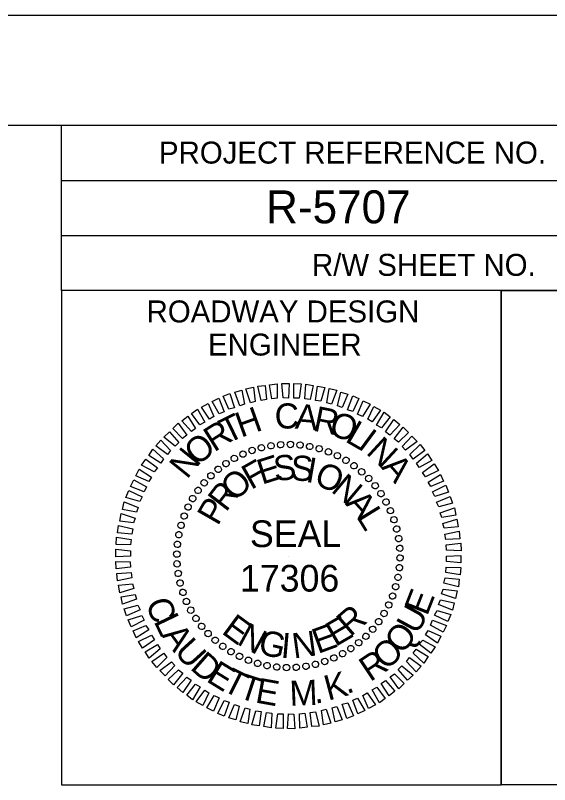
# Model space of a CAD drawing. Extents: x 573078 to 573117.1, y -55221.3 to -55199.3.
# Drawn here: x 573107.304 to 573109.734, y -55202.8 to -55199.298 of the extents above; entities that cross this region are included whole.
import ezdxf

# ---------------------------------------------------------------- set-up
doc = ezdxf.new("R2010")
doc.units = 0
for name, color, linetype in [('Prop Dimension', 7, 'Continuous'), ('Scratch_Level_1', 7, 'Continuous'), ('Sheet Data Field CELL', 7, 'Continuous'), ('Sheet Plan CELL', 7, 'Continuous'), ('Sheet Plot Border Inside CELL', 7, 'Continuous')]:
    doc.layers.add(name, color=color, linetype=linetype)

msp = doc.modelspace()

# ---------------------------------------------------------------- linework, layer by layer
at = {"layer": 'Prop Dimension'}
for p, q in [((573108.5105, -55201.2518), (573108.5105, -55201.2518)), ((573108.555, -55201.2509), (573108.555, -55201.2509)), ((573108.5996, -55201.2539), (573108.5996, -55201.2539)), ((573108.38, -55201.2782), (573108.38, -55201.2782)), ((573108.4225, -55201.266), (573108.4225, -55201.266)), ((573108.467, -55201.2579), (573108.467, -55201.2579)), ((573108.6432, -55201.2611), (573108.6432, -55201.2611)), ((573108.6857, -55201.2701), (573108.6857, -55201.2701)), ((573108.7283, -55201.2842), (573108.7283, -55201.2842)), ((573108.2999, -55201.3146), (573108.2999, -55201.3146)), ((573108.3395, -55201.2944), (573108.3395, -55201.2944)), ((573108.7688, -55201.3025), (573108.7688, -55201.3025)), ((573108.8081, -55201.3227), (573108.8081, -55201.3227)), ((573108.2614, -55201.338), (573108.2614, -55201.338)), ((573108.8446, -55201.3481), (573108.8446, -55201.3481)), ((573108.1925, -55201.3936), (573108.1925, -55201.3936)), ((573108.2261, -55201.3632), (573108.2261, -55201.3632)), ((573108.8801, -55201.3754), (573108.8801, -55201.3754)), ((573108.1622, -55201.4251), (573108.1622, -55201.4251)), ((573108.9114, -55201.4057), (573108.9114, -55201.4057)), ((573108.1349, -55201.4604), (573108.1349, -55201.4604)), ((573108.9418, -55201.4393), (573108.9418, -55201.4393)), ((573108.1095, -55201.4969), (573108.1095, -55201.4969)), ((573108.9672, -55201.4746), (573108.9672, -55201.4746)), ((573108.0893, -55201.5365), (573108.0893, -55201.5365)), ((573108.9904, -55201.5131), (573108.9904, -55201.5131)), ((573109.0106, -55201.5527), (573109.0106, -55201.5527)), ((573108.071, -55201.577), (573108.071, -55201.577)), ((573109.0268, -55201.5932), (573109.0268, -55201.5932)), ((573108.0569, -55201.6195), (573108.0569, -55201.6195)), ((573109.039, -55201.6357), (573109.039, -55201.6357)), ((573108.0479, -55201.662), (573108.0479, -55201.662)), ((573108.0407, -55201.7054), (573108.0407, -55201.7054)), ((573109.0471, -55201.6802), (573109.0471, -55201.6802)), ((573109.0532, -55201.7237), (573109.0532, -55201.7237)), ((573108.0377, -55201.75), (573108.0377, -55201.75)), ((573108.546, -55201.7592), (573108.546, -55201.7592)), ((573109.0543, -55201.7682), (573109.0543, -55201.7682)), ((573108.0386, -55201.7945), (573108.0386, -55201.7945)), ((573109.0511, -55201.8128), (573109.0511, -55201.8128)), ((573108.0447, -55201.8382), (573108.0447, -55201.8382)), ((573108.0528, -55201.8827), (573108.0528, -55201.8827)), ((573109.0442, -55201.8564), (573109.0442, -55201.8564)), ((573109.0349, -55201.8989), (573109.0349, -55201.8989)), ((573108.065, -55201.9253), (573108.065, -55201.9253)), ((573109.0208, -55201.9415), (573109.0208, -55201.9415)), ((573108.0812, -55201.9658), (573108.0812, -55201.9658)), ((573109.0025, -55201.982), (573109.0025, -55201.982)), ((573108.1014, -55202.0051), (573108.1014, -55202.0051)), ((573108.9823, -55202.0213), (573108.9823, -55202.0213)), ((573108.1248, -55202.0436), (573108.1248, -55202.0436)), ((573108.9571, -55202.0578), (573108.9571, -55202.0578)), ((573108.15, -55202.0792), (573108.15, -55202.0792)), ((573108.9296, -55202.0933), (573108.9296, -55202.0933)), ((573108.1804, -55202.1125), (573108.1804, -55202.1125)), ((573108.8993, -55202.1246), (573108.8993, -55202.1246)), ((573108.2119, -55202.1428), (573108.2119, -55202.1428)), ((573108.866, -55202.155), (573108.866, -55202.155)), ((573108.2472, -55202.1703), (573108.2472, -55202.1703)), ((573108.2837, -55202.1955), (573108.2837, -55202.1955)), ((573108.8304, -55202.1804), (573108.8304, -55202.1804)), ((573108.3233, -55202.2157), (573108.3233, -55202.2157)), ((573108.3638, -55202.234), (573108.3638, -55202.234)), ((573108.7526, -55202.2238), (573108.7526, -55202.2238)), ((573108.7919, -55202.2036), (573108.7919, -55202.2036)), ((573108.4063, -55202.2481), (573108.4063, -55202.2481)), ((573108.4488, -55202.2574), (573108.4488, -55202.2574)), ((573108.4922, -55202.2643), (573108.4922, -55202.2643)), ((573108.5368, -55202.2675), (573108.5368, -55202.2675)), ((573108.5813, -55202.2664), (573108.5813, -55202.2664)), ((573108.625, -55202.2603), (573108.625, -55202.2603)), ((573108.6695, -55202.2522), (573108.6695, -55202.2522)), ((573108.7121, -55202.24), (573108.7121, -55202.24))]:
    msp.add_line(p, q, dxfattribs=at)
for points in [[(573108.4711, -55201.0444), (573108.4598, -55200.9796), (573108.4943, -55200.9755), (573108.4954, -55201.0412)], [(573108.5217, -55201.0392), (573108.5165, -55200.9735), (573108.5501, -55200.9744), (573108.546, -55201.0403)], [(573108.5703, -55201.0403), (573108.5703, -55200.9744), (573108.6036, -55200.9755), (573108.5946, -55201.0412)], [(573108.3253, -55201.0748), (573108.3019, -55201.014), (573108.3334, -55201.0048), (573108.3464, -55201.0676)], [(573108.3739, -55201.0615), (573108.3525, -55200.9978), (573108.3869, -55200.9906), (573108.395, -55201.0565)], [(573108.4225, -55201.0505), (573108.4063, -55200.9857), (573108.4396, -55200.9825), (573108.4468, -55201.0473)], [(573108.6209, -55201.0433), (573108.625, -55200.9776), (573108.6583, -55200.9836), (573108.6452, -55201.0473)], [(573108.6695, -55201.0514), (573108.6785, -55200.9866), (573108.7121, -55200.9917), (573108.6938, -55201.0545)], [(573108.7211, -55201.0626), (573108.7312, -55200.9967), (573108.7656, -55201.0048), (573108.7424, -55201.0676)], [(573108.231, -55201.1121), (573108.1986, -55201.0554), (573108.2301, -55201.0412), (573108.2533, -55201.1031)], [(573108.2756, -55201.091), (573108.2492, -55201.0322), (573108.2796, -55201.0201), (573108.301, -55201.0849)], [(573108.7697, -55201.0757), (573108.785, -55201.0129), (573108.8162, -55201.023), (573108.791, -55201.0829)], [(573108.8153, -55201.0939), (573108.8385, -55201.0302), (573108.8669, -55201.0424), (573108.8385, -55201.1011)], [(573108.1876, -55201.1364), (573108.15, -55201.0817), (573108.1815, -55201.0655), (573108.2067, -55201.1243)], [(573108.8608, -55201.1132), (573108.8862, -55201.0534), (573108.9175, -55201.0676), (573108.8831, -55201.1243)], [(573108.9074, -55201.1364), (573108.9348, -55201.0788), (573108.9652, -55201.0959), (573108.9267, -55201.1486)], [(573108.143, -55201.1618), (573108.1055, -55201.1101), (573108.1318, -55201.091), (573108.1653, -55201.1497)], [(573108.947, -55201.1639), (573108.9823, -55201.1051), (573109.0086, -55201.1263), (573108.9692, -55201.176)], [(573108.1046, -55201.1922), (573108.0609, -55201.1436), (573108.0884, -55201.1222), (573108.1237, -55201.1789)], [(573108.9884, -55201.1942), (573109.0259, -55201.1384), (573109.0523, -55201.1607), (573109.0077, -55201.2084)], [(573108.0641, -55201.2235), (573108.0195, -55201.1789), (573108.0438, -55201.1546), (573108.0832, -55201.2093)], [(573109.0268, -55201.2255), (573109.0685, -55201.1729), (573109.0928, -55201.1972), (573109.0462, -55201.2408)], [(573108.0305, -55201.259), (573107.979, -55201.2174), (573108.0042, -55201.1942), (573108.0467, -55201.2428)], [(573109.0633, -55201.2611), (573109.1069, -55201.2134), (573109.1312, -55201.2377), (573109.0786, -55201.2773)], [(573107.9952, -55201.2975), (573107.9426, -55201.2579), (573107.9648, -55201.2316), (573108.0094, -55201.2793)], [(573109.0988, -55201.2975), (573109.1454, -55201.2518), (573109.1666, -55201.2793), (573109.113, -55201.3178)], [(573107.9648, -55201.336), (573107.9102, -55201.3016), (573107.9293, -55201.2721), (573107.9779, -55201.3166)], [(573107.9345, -55201.3765), (573107.8778, -55201.3461), (573107.898, -55201.3178), (573107.9507, -55201.3583)], [(573109.1292, -55201.3369), (573109.1787, -55201.2944), (573109.1981, -55201.3238), (573109.1414, -55201.3562)], [(573109.1555, -55201.3785), (573109.2091, -55201.34), (573109.2284, -55201.3704), (573109.1697, -55201.3988)], [(573107.9102, -55201.4199), (573107.8523, -55201.3947), (573107.8676, -55201.3632), (573107.9223, -55201.4008)], [(573109.1819, -55201.4231), (573109.2386, -55201.3875), (573109.2516, -55201.419), (573109.194, -55201.4422)], [(573107.8899, -55201.4665), (573107.8271, -55201.4433), (573107.8422, -55201.4118), (573107.9, -55201.4442)], [(573107.8697, -55201.511), (573107.8069, -55201.4928), (573107.8199, -55201.4615), (573107.8807, -55201.4899)], [(573109.2021, -55201.4665), (573109.2617, -55201.4361), (573109.275, -55201.4685), (573109.2122, -55201.4888)], [(573109.2203, -55201.5142), (573109.282, -55201.4879), (573109.2932, -55201.5191), (573109.2305, -55201.5353)], [(573107.8544, -55201.5596), (573107.7916, -55201.5466), (573107.7988, -55201.5131), (573107.8625, -55201.5385)], [(573107.8413, -55201.6082), (573107.7785, -55201.6001), (573107.7855, -55201.5657), (573107.8494, -55201.5871)], [(573109.2365, -55201.5628), (573109.3013, -55201.5394), (573109.3074, -55201.5729), (573109.2435, -55201.5839)], [(573109.2487, -55201.6114), (573109.3124, -55201.592), (573109.3184, -55201.6265), (573109.2548, -55201.6325)], [(573107.8332, -55201.66), (573107.7684, -55201.6539), (573107.7725, -55201.6195), (573107.8382, -55201.6357)], [(573107.828, -55201.7086), (573107.7623, -55201.7066), (573107.7644, -55201.673), (573107.8301, -55201.6843)], [(573109.2577, -55201.66), (573109.3236, -55201.6458), (573109.3265, -55201.6802), (573109.2617, -55201.6843)], [(573109.2638, -55201.7086), (573109.3297, -55201.7005), (573109.3317, -55201.7349), (573109.2658, -55201.7329)], [(573107.8271, -55201.7592), (573107.7612, -55201.7621), (573107.7612, -55201.7277), (573107.8271, -55201.7349)], [(573109.2649, -55201.7592), (573109.3306, -55201.7561), (573109.3306, -55201.7905), (573109.2649, -55201.7835)], [(573107.828, -55201.8098), (573107.7623, -55201.8179), (573107.7603, -55201.7835), (573107.826, -55201.7855)], [(573109.2638, -55201.8098), (573109.3297, -55201.8119), (573109.3277, -55201.8452), (573109.2617, -55201.8341)], [(573107.8341, -55201.8584), (573107.7684, -55201.8726), (573107.7653, -55201.8382), (573107.8301, -55201.8341)], [(573107.8433, -55201.907), (573107.7794, -55201.9262), (573107.7734, -55201.8917), (573107.8373, -55201.8857)], [(573109.2588, -55201.8584), (573109.3236, -55201.8645), (573109.3196, -55201.8989), (573109.2536, -55201.8827)], [(573109.2507, -55201.91), (573109.3135, -55201.9181), (573109.3063, -55201.9525), (573109.2426, -55201.9313)], [(573107.8555, -55201.9556), (573107.7907, -55201.9788), (573107.7846, -55201.9455), (573107.8483, -55201.9343)], [(573107.8717, -55202.0042), (573107.8098, -55202.0306), (573107.7988, -55201.9991), (573107.8616, -55201.9829)], [(573109.2374, -55201.9586), (573109.3002, -55201.9718), (573109.2932, -55202.0051), (573109.2293, -55201.9799)], [(573109.2224, -55202.0072), (573109.2851, -55202.0254), (573109.2719, -55202.0569), (573109.2111, -55202.0285)], [(573107.8899, -55202.0517), (573107.8301, -55202.0821), (573107.817, -55202.0497), (573107.8798, -55202.0294)], [(573109.2021, -55202.0517), (573109.2649, -55202.0751), (573109.2496, -55202.1064), (573109.192, -55202.074)], [(573107.9102, -55202.0954), (573107.8535, -55202.1307), (573107.8402, -55202.0994), (573107.898, -55202.076)], [(573107.9365, -55202.1399), (573107.8827, -55202.1784), (573107.8636, -55202.148), (573107.9223, -55202.1197)], [(573109.1819, -55202.0983), (573109.2395, -55202.1237), (573109.2244, -55202.155), (573109.1697, -55202.1176)], [(573107.9628, -55202.1813), (573107.9131, -55202.2238), (573107.894, -55202.1946), (573107.9507, -55202.1622)], [(573109.1576, -55202.1419), (573109.2143, -55202.1723), (573109.194, -55202.2007), (573109.1414, -55202.1602)], [(573107.9932, -55202.2209), (573107.9466, -55202.2664), (573107.9252, -55202.2391), (573107.979, -55202.2007)], [(573109.1272, -55202.1824), (573109.1819, -55202.2169), (573109.1625, -55202.2461), (573109.1139, -55202.2016)], [(573109.0968, -55202.2209), (573109.1495, -55202.2603), (573109.1272, -55202.2866), (573109.0826, -55202.2391)], [(573108.0285, -55202.2574), (573107.9851, -55202.3048), (573107.9608, -55202.2805), (573108.0134, -55202.2412)], [(573109.0613, -55202.2594), (573109.113, -55202.3008), (573109.0876, -55202.3242), (573109.0451, -55202.2756)], [(573108.065, -55202.2927), (573108.0236, -55202.3453), (573107.9993, -55202.321), (573108.0458, -55202.2776)], [(573109.028, -55202.2947), (573109.0725, -55202.3393), (573109.0482, -55202.3636), (573109.0086, -55202.3089)], [(573108.1034, -55202.3242), (573108.0661, -55202.3798), (573108.0398, -55202.3575), (573108.0843, -55202.31)], [(573108.1451, -55202.3546), (573108.1095, -55202.4133), (573108.0832, -55202.3919), (573108.1228, -55202.3424)], [(573108.9875, -55202.3262), (573109.0309, -55202.3748), (573109.0037, -55202.396), (573108.9681, -55202.3393)], [(573108.1844, -55202.3818), (573108.1572, -55202.4396), (573108.1268, -55202.4223), (573108.1653, -55202.3696)], [(573108.949, -55202.3566), (573108.9863, -55202.4081), (573108.96, -55202.4275), (573108.9267, -55202.3687)], [(573108.231, -55202.4052), (573108.2058, -55202.4648), (573108.1743, -55202.4506), (573108.2087, -55202.3939)], [(573108.8608, -55202.4061), (573108.8932, -55202.4628), (573108.8619, -55202.477), (573108.8385, -55202.4153)], [(573108.9044, -55202.3818), (573108.9418, -55202.4365), (573108.9105, -55202.4527), (573108.8851, -55202.3939)], [(573108.2767, -55202.4243), (573108.2533, -55202.4882), (573108.2249, -55202.4761), (573108.2533, -55202.4173)], [(573108.3221, -55202.4425), (573108.3071, -55202.5053), (573108.2756, -55202.4952), (573108.301, -55202.4356)], [(573108.7667, -55202.4437), (573108.7899, -55202.5044), (573108.7586, -55202.5134), (573108.7454, -55202.4506)], [(573108.8162, -55202.4275), (573108.8426, -55202.4862), (573108.8122, -55202.4983), (573108.791, -55202.4335)], [(573108.3707, -55202.4558), (573108.3606, -55202.5215), (573108.3262, -55202.5134), (573108.3496, -55202.4506)], [(573108.4225, -55202.4668), (573108.4133, -55202.5316), (573108.38, -55202.5267), (573108.3982, -55202.4639)], [(573108.4711, -55202.4749), (573108.467, -55202.5409), (573108.4335, -55202.5348), (573108.4468, -55202.4709)], [(573108.5217, -55202.4781), (573108.5217, -55202.5438), (573108.4882, -55202.5429), (573108.4974, -55202.477)], [(573108.5703, -55202.479), (573108.5753, -55202.5449), (573108.542, -55202.5438), (573108.546, -55202.4781)], [(573108.6209, -55202.474), (573108.632, -55202.5388), (573108.5975, -55202.5429), (573108.5966, -55202.477)], [(573108.6695, -55202.468), (573108.6857, -55202.5328), (573108.6522, -55202.5357), (573108.6452, -55202.4709)], [(573108.7181, -55202.4567), (573108.7393, -55202.5206), (573108.7049, -55202.5276), (573108.6968, -55202.4619)]]:
    msp.add_lwpolyline(points, close=True, dxfattribs=at)
for centre, major_axis in [((573108.4232, -55201.2664), (-0.0035, 0.0141)), ((573108.4666, -55201.2575), (-0.0023, 0.0144)), ((573108.5106, -55201.2525), (-0.001, 0.0145)), ((573108.5549, -55201.2514), (0.0003, 0.0146)), ((573108.5991, -55201.2541), (0.0015, 0.0145)), ((573108.6429, -55201.2606), (0.0028, 0.0143)), ((573108.686, -55201.271), (0.004, 0.014)), ((573108.3394, -55201.2952), (-0.0059, 0.0133)), ((573108.3807, -55201.2789), (-0.0047, 0.0138)), ((573108.728, -55201.285), (0.0052, 0.0136)), ((573108.7687, -55201.3027), (0.0064, 0.0131)), ((573108.262, -55201.3381), (-0.0082, 0.0121)), ((573108.2998, -55201.315), (-0.0071, 0.0128)), ((573108.8076, -55201.3238), (0.0075, 0.0125)), ((573108.2264, -55201.3645), (-0.0092, 0.0113)), ((573108.8445, -55201.3483), (0.0086, 0.0118)), ((573108.8792, -55201.3759), (0.0096, 0.011)), ((573108.1932, -55201.3938), (-0.0101, 0.0105)), ((573108.9113, -55201.4064), (0.0105, 0.0101)), ((573108.1627, -55201.426), (-0.011, 0.0096)), ((573108.9407, -55201.4395), (0.0113, 0.0092)), ((573108.1351, -55201.4606), (-0.0118, 0.0086)), ((573108.9671, -55201.4751), (0.0121, 0.0082)), ((573108.1107, -55201.4976), (-0.0125, 0.0075)), ((573108.9902, -55201.5129), (0.0128, 0.0071)), ((573108.0895, -55201.5365), (-0.0131, 0.0064)), ((573109.01, -55201.5526), (0.0133, 0.0059)), ((573108.0719, -55201.5771), (-0.0136, 0.0052)), ((573108.0578, -55201.6192), (-0.014, 0.004)), ((573109.0262, -55201.5938), (0.0138, 0.0047)), ((573109.0388, -55201.6363), (0.0141, 0.0035)), ((573108.0475, -55201.6622), (-0.0143, 0.0028)), ((573109.0476, -55201.6797), (0.0144, 0.0023)), ((573108.0409, -55201.7061), (-0.0145, 0.0015)), ((573109.0527, -55201.7237), (0.0145, 0.001)), ((573108.0382, -55201.7503), (-0.0146, 0.0003)), ((573108.0394, -55201.7946), (-0.0145, -0.001)), ((573109.0538, -55201.768), (0.0146, -0.0003)), ((573109.0511, -55201.8122), (0.0145, -0.0015)), ((573108.0444, -55201.8386), (-0.0144, -0.0023)), ((573109.0446, -55201.8561), (0.0143, -0.0028)), ((573108.0532, -55201.882), (-0.0141, -0.0035)), ((573109.0342, -55201.8991), (0.014, -0.004)), ((573108.0658, -55201.9245), (-0.0138, -0.0047)), ((573108.0821, -55201.9657), (-0.0133, -0.0059)), ((573109.0202, -55201.9412), (0.0136, -0.0052)), ((573108.1018, -55202.0054), (-0.0128, -0.0071)), ((573109.0025, -55201.9818), (0.0131, -0.0064)), ((573108.125, -55202.0431), (-0.0121, -0.0082)), ((573108.9813, -55202.0207), (0.0125, -0.0075)), ((573108.1513, -55202.0788), (-0.0113, -0.0092)), ((573108.9569, -55202.0577), (0.0118, -0.0086)), ((573108.1807, -55202.1119), (-0.0105, -0.0101)), ((573108.9293, -55202.0923), (0.011, -0.0096)), ((573108.2128, -55202.1424), (-0.0096, -0.011)), ((573108.8988, -55202.1245), (0.0101, -0.0105)), ((573108.2475, -55202.17), (-0.0086, -0.0118)), ((573108.83, -55202.1802), (0.0082, -0.0121)), ((573108.8656, -55202.1538), (0.0092, -0.0113)), ((573108.2844, -55202.1945), (-0.0075, -0.0125)), ((573108.3234, -55202.2156), (-0.0064, -0.0131)), ((573108.7922, -55202.2033), (0.0071, -0.0128)), ((573108.364, -55202.2333), (-0.0052, -0.0136)), ((573108.406, -55202.2473), (-0.004, -0.014)), ((573108.6689, -55202.2519), (0.0035, -0.0141)), ((573108.7114, -55202.2393), (0.0047, -0.0138)), ((573108.7526, -55202.2231), (0.0059, -0.0133)), ((573108.4491, -55202.2577), (-0.0028, -0.0143)), ((573108.4929, -55202.2642), (-0.0015, -0.0145)), ((573108.5372, -55202.2669), (-0.0003, -0.0146)), ((573108.5814, -55202.2658), (0.001, -0.0145)), ((573108.6255, -55202.2608), (0.0023, -0.0144))]:
    msp.add_ellipse(centre, major_axis=major_axis, ratio=0.999708, dxfattribs=at)
at = {"layer": 'Scratch_Level_1'}
msp.add_line((573108.546, -55201.7592), (573108.546, -55201.7592), dxfattribs=at)
at = {"layer": 'Sheet Plan CELL'}
for p, q in [((573107.5132, -55200.0494), (573111.5142, -55200.0497)), ((573107.5132, -55200.3002), (573111.5142, -55200.2997)), ((573109.5142, -55200.5499), (573109.5144, -55202.7992))]:
    msp.add_line(p, q, dxfattribs=at)
for points in [[(573081.5142, -55199.7984), (573111.5142, -55199.7984), (573111.5142, -55220.7984), (573081.5142, -55220.7984)], [(573107.5132, -55199.7984), (573111.5142, -55199.7984), (573111.5142, -55200.5499), (573107.5132, -55200.5499)], [(573109.5142, -55200.5499), (573107.5132, -55200.5499), (573107.5132, -55202.7999), (573109.5142, -55202.7999)], [(573109.5142, -55200.5499), (573111.5142, -55200.5499), (573111.5142, -55202.7999), (573109.5142, -55202.7999)]]:
    msp.add_lwpolyline(points, close=True, dxfattribs=at)
at = {"layer": 'Sheet Plot Border Inside CELL'}
msp.add_lwpolyline([(573112.0142, -55199.2984), (573078.0142, -55199.2984), (573078.0142, -55221.2984), (573112.0142, -55221.2984)], close=True, dxfattribs=at)

# ---------------------------------------------------------------- texts
at = {"layer": 'Prop Dimension'}
for s, height, rotation, p in [('H', 0.1144, 19.8207, (573108.3305, -55201.2212)), ('C', 0.1144, 1.0718, (573108.4844, -55201.1798)), ('A', 0.1144, 354.8222, (573108.5735, -55201.1787)), ('R', 0.1144, 348.5725, (573108.6545, -55201.1879)), ('T', 0.1144, 26.0703, (573108.2688, -55201.2496)), ('O', 0.1144, 342.3229, (573108.7253, -55201.2062)), ('R', 0.1144, 32.3199, (573108.2081, -55201.2881)), ('L', 0.1144, 329.8237, (573108.7994, -55201.2354)), ('I', 0.1144, 323.5741, (573108.8561, -55201.2649)), ('O', 0.1144, 38.5695, (573108.13, -55201.352)), ('N', 0.1144, 317.3244, (573108.8954, -55201.2912)), ('N', 0.1144, 51.0688, (573108.0845, -55201.4127)), ('F', 0.1144, 29.3, (573108.3761, -55201.4593)), ('E', 0.1144, 17.6709, (573108.4256, -55201.435)), ('S', 0.1144, 6.1833, (573108.4844, -55201.4188)), ('S', 0.1144, 358.4778, (573108.5564, -55201.4156)), ('I', 0.1144, 350.0931, (573108.6212, -55201.4208)), ('A', 0.1144, 311.0748, (573108.9654, -55201.3569)), ('O', 0.1144, 335.3611, (573108.6565, -55201.4278)), ('O', 0.1144, 43.5875, (573108.3041, -55201.514)), ('N', 0.1144, 319.95, (573108.7355, -55201.4633)), ('R', 0.1144, 52.4166, (573108.2616, -55201.5626)), ('P', 0.1144, 60.1222, (573108.2243, -55201.6253)), ('A', 0.1144, 312.2445, (573108.8023, -55201.523)), ('L', 0.1144, 301.6752, (573108.8529, -55201.5797)), ('SEAL', 0.1215, 0, (573108.371, -55201.7185)), ('17306', 0.1215, 0, (573108.3255, -55201.921)), ('E', 0.1144, 68.6635, (573109.1769, -55202.0353)), ('C', 0.1144, 287.4003, (573107.8971, -55201.9685)), ('R', 0.1144, 40.7353, (573108.8277, -55202.1296)), ('U', 0.1144, 61.3078, (573109.1324, -55202.1203)), ('L', 0.1144, 295.5141, (573107.9315, -55202.0555)), ('E', 0.1144, 323.6798, (573108.2373, -55202.1082)), ('E', 0.1144, 30.1214, (573108.7598, -55202.1741)), ('A', 0.1144, 306.1492, (573107.9671, -55202.1203)), ('N', 0.1144, 331.3854, (573108.3073, -55202.1579)), ('G', 0.1144, 346.7965, (573108.4034, -55202.2025)), ('E', 0.1144, 20.0411, (573108.6799, -55202.2054)), ('Q', 0.1144, 52.3928, (573109.0646, -55202.2106)), ('U', 0.1144, 312.3988, (573108.0227, -55202.1973)), ('I', 0.1144, 355.0405, (573108.5087, -55202.2216)), ('N', 0.1144, 7.7341, (573108.5705, -55202.2256)), ('O', 0.1144, 39.8936, (573108.9877, -55202.2823)), ('D', 0.1144, 318.6484, (573108.0947, -55202.2713)), ('R', 0.1144, 33.6439, (573108.9177, -55202.3341)), ('E', 0.1144, 328.3523, (573108.1676, -55202.3269)), ('T', 0.1144, 333.6523, (573108.2393, -55202.3674)), ('T', 0.1144, 341.812, (573108.3122, -55202.4018)), ('K', 0.1144, 14.8951, (573108.7265, -55202.418)), ('E', 0.1144, 349.8966, (573108.3912, -55202.4252)), ('M', 0.1144, 2.3958, (573108.5532, -55202.4414)), ('.', 0.1144, 21.1447, (573108.8124, -55202.3888)), ('.', 0.1144, 8.6454, (573108.6666, -55202.4313))]:
    msp.add_text(s, height=height, rotation=rotation, dxfattribs=at).set_placement(p)
at = {"layer": 'Sheet Data Field CELL'}
msp.add_text('R-5707', height=0.15, rotation=0, dxfattribs=at).set_placement((573108.4444, -55200.2449))
at = {"layer": 'Sheet Plan CELL'}
for s, height, p in [('PROJECT REFERENCE NO.', 0.100002, (573107.9572, -55199.9729)), ('R/W SHEET NO.', 0.100002, (573108.6532, -55200.4839)), ('ROADWAY DESIGN', 0.100002, (573107.9007, -55200.6959)), ('ENGINEER', 0.1, (573108.1804, -55200.8467))]:
    msp.add_text(s, height=height, rotation=0, dxfattribs=at).set_placement(p)

doc.saveas('drawing.dxf')
